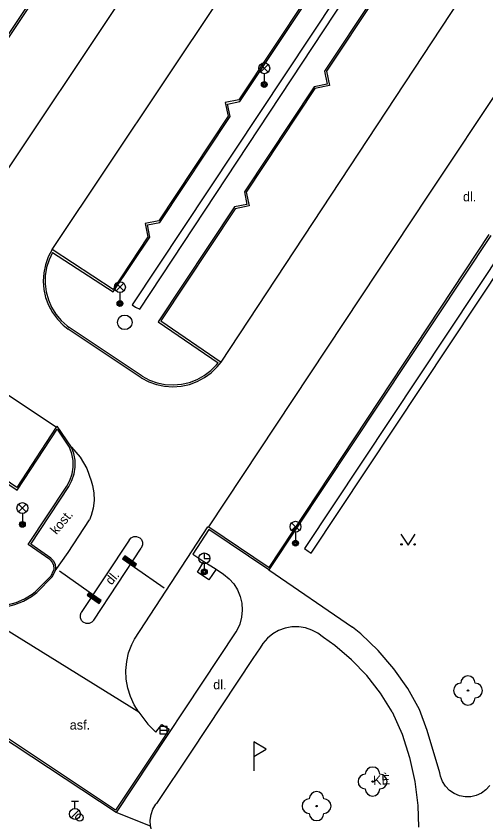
# Model space of a CAD drawing. Extents: x -539515 to -538098, y -1182060 to -1180157.
# Drawn here: x -538339.6 to -538307.3, y -1181540.3 to -1181484.8 of the extents above; entities that cross this region are included whole.
import ezdxf

# ---------------------------------------------------------------- set-up
doc = ezdxf.new("R2010")
doc.units = 0
for name, color, linetype in [('Vrstva 13', 7, 'Continuous'), ('Vrstva 22', 7, 'Continuous'), ('Vrstva 27', 7, 'Continuous'), ('Vrstva 28', 7, 'Continuous'), ('Vrstva 31', 7, 'Continuous'), ('Vrstva 33', 7, 'Continuous'), ('Vrstva 36', 7, 'Continuous'), ('Vrstva 40', 7, 'Continuous'), ('Vrstva 88', 7, 'Continuous')]:
    doc.layers.add(name, color=color, linetype=linetype)

msp = doc.modelspace()

# ---------------------------------------------------------------- linework, layer by layer
at = {"layer": 'Vrstva 13'}
for p, q in [((-538329.87, -1181470.61), (-538351.69, -1181503.32)), ((-538347.372, -1181506.094), (-538325.65, -1181473.54)), ((-538337.14, -1181500.86), (-538320.82, -1181476.41)), ((-538315.63, -1181480.58), (-538331.61, -1181504.66)), ((-538331.09, -1181504.96), (-538315.23, -1181480.93)), ((-538313.49, -1181481.218), (-538318.372, -1181488.571)), ((-538325.5, -1181508.61), (-538309.04, -1181483.64)), ((-538324.197, -1181490.668), (-538319.334, -1181483.335)), ((-538311.2, -1181497.12), (-538304.32, -1181486.74)), ((-538319.089, -1181489.652), (-538323.894, -1181496.889)), ((-538329.714, -1181498.989), (-538324.878, -1181491.694)), ((-538326.34, -1181519.96), (-538311.2, -1181497.12)), ((-538324.581, -1181497.924), (-538329.83, -1181505.83)), ((-538306.92, -1181499.89), (-538322.2, -1181522.92)), ((-538305.86, -1181500.51), (-538319.76, -1181521.45)), ((-538319.29, -1181521.77), (-538305.43, -1181500.87)), ((-538337.106, -1181501.059), (-538332.94, -1181503.77)), ((-538329.83, -1181505.83), (-538325.699, -1181508.657)), ((-538336.85, -1181513.09), (-538347.26, -1181506.17)), ((-538330.925, -1181509.577), (-538335.951, -1181506.227)), ((-538350.19, -1181510.38), (-538339.54, -1181517.42)), ((-538339.54, -1181517.42), (-538336.79, -1181513.23)), ((-538336.79, -1181513.23), (-538335.915, -1181514.522)), ((-538322.2, -1181522.92), (-538316.44, -1181526.85)), ((-538331.16, -1181532.72), (-538343.95, -1181524.79)), ((-538324.47, -1181527.17), (-538332.734, -1181539.625)), ((-538322.803, -1181528.276), (-538323.31, -1181529.01)), ((-538323.31, -1181529.01), (-538327.59, -1181535.47)), ((-538332.734, -1181539.625), (-538347.28, -1181530)), ((-538327.59, -1181535.47), (-538329.95, -1181539.01)), ((-538330.35, -1181540.57), (-538332.734, -1181539.625))]:
    msp.add_line(p, q, dxfattribs=at)
for points in [[(-538318.372, -1181488.571), (-538318.19, -1181489.47), (-538319.089, -1181489.652)], [(-538324.878, -1181491.694), (-538325.05, -1181490.84), (-538324.197, -1181490.668)], [(-538323.894, -1181496.889), (-538323.72, -1181497.75), (-538324.581, -1181497.924)], [(-538332.94, -1181503.77), (-538330.395, -1181500.016), (-538330.567, -1181499.162), (-538329.714, -1181498.989)], [(-538337.106, -1181501.059), (-538337.347, -1181501.566), (-538337.513, -1181502.103), (-538337.602, -1181502.658), (-538337.611, -1181503.22), (-538337.54, -1181503.778), (-538337.391, -1181504.32), (-538337.166, -1181504.835), (-538336.871, -1181505.314), (-538336.51, -1181505.745), (-538336.093, -1181506.121), (-538335.951, -1181506.227)], [(-538331.61, -1181504.66), (-538331.39, -1181504.82), (-538331.09, -1181504.96)], [(-538330.925, -1181509.577), (-538330.426, -1181509.84), (-538329.896, -1181510.03), (-538329.344, -1181510.143), (-538328.781, -1181510.177), (-538328.219, -1181510.131), (-538327.67, -1181510.006), (-538327.143, -1181509.804), (-538326.651, -1181509.53), (-538326.202, -1181509.189), (-538325.806, -1181508.788), (-538325.699, -1181508.657)], [(-538336.13, -1181517.157), (-538335.905, -1181516.75), (-538335.753, -1181516.311), (-538335.678, -1181515.852), (-538335.682, -1181515.387), (-538335.767, -1181514.93), (-538335.915, -1181514.522)], [(-538335.8, -1181514.46), (-538335.21, -1181515.153), (-538334.75, -1181515.939), (-538334.434, -1181516.793), (-538334.36, -1181517.1)], [(-538337.29, -1181522.2), (-538338.79, -1181521.16), (-538336.13, -1181517.157)], [(-538334.36, -1181517.1), (-538334.26, -1181517.613), (-538334.239, -1181518.135), (-538334.298, -1181518.655), (-538334.436, -1181519.159), (-538334.56, -1181519.46)], [(-538336.93, -1181522.99), (-538336.04, -1181521.71), (-538334.56, -1181519.46)], [(-538322.2, -1181522.92), (-538326.34, -1181520.14), (-538327.44, -1181521.83), (-538326.69, -1181522.33), (-538325.84, -1181522.87), (-538325.32, -1181523.22)], [(-538319.76, -1181521.45), (-538319.49, -1181521.62), (-538319.29, -1181521.77)], [(-538337.29, -1181522.2), (-538337.136, -1181522.376), (-538337.043, -1181522.6), (-538337.026, -1181522.842), (-538337.048, -1181522.959)], [(-538325.84, -1181522.87), (-538326.33, -1181523.59), (-538327.13, -1181523.07), (-538326.69, -1181522.33)], [(-538338.27, -1181524.401), (-538337.21, -1181523.321), (-538337.048, -1181522.959)], [(-538325.32, -1181523.22), (-538324.944, -1181523.524), (-538324.623, -1181523.885), (-538324.366, -1181524.295), (-538324.18, -1181524.741), (-538324.07, -1181525.21), (-538324.039, -1181525.694), (-538324.087, -1181526.175), (-538324.215, -1181526.641), (-538324.417, -1181527.08), (-538324.47, -1181527.17)], [(-538343.77, -1181524.73), (-538343.224, -1181525.021), (-538342.646, -1181525.239), (-538342.044, -1181525.38), (-538341.429, -1181525.443), (-538340.811, -1181525.426), (-538340.201, -1181525.329), (-538339.608, -1181525.154), (-538339.043, -1181524.904), (-538338.514, -1181524.584), (-538338.27, -1181524.401)], [(-538318.45, -1181527.57), (-538318.822, -1181527.279), (-538319.237, -1181527.054), (-538319.685, -1181526.903), (-538320.151, -1181526.829), (-538320.623, -1181526.835), (-538321.088, -1181526.921), (-538321.531, -1181527.083), (-538321.941, -1181527.318), (-538322.305, -1181527.619), (-538322.614, -1181527.977), (-538322.803, -1181528.276)], [(-538311.82, -1181532.52), (-538312.64, -1181531.079), (-538313.595, -1181529.724), (-538314.676, -1181528.468), (-538315.874, -1181527.321), (-538316.44, -1181526.85)], [(-538313.7, -1181532.69), (-538314.507, -1181531.397), (-538315.445, -1181530.195), (-538316.504, -1181529.098), (-538317.671, -1181528.118), (-538318.45, -1181527.57)], [(-538310.42, -1181536.88), (-538311.293, -1181533.963), (-538311.82, -1181532.52)], [(-538313.7, -1181532.69), (-538313.031, -1181534.234), (-538312.512, -1181535.834), (-538312.148, -1181537.476), (-538311.94, -1181539.146), (-538311.89, -1181540.63)], [(-538306.99, -1181537.76), (-538307.251, -1181538.05), (-538307.565, -1181538.281), (-538307.919, -1181538.443), (-538308.299, -1181538.53), (-538308.689, -1181538.537), (-538309.072, -1181538.465), (-538309.433, -1181538.316), (-538309.755, -1181538.097), (-538310.027, -1181537.817), (-538310.235, -1181537.488), (-538310.373, -1181537.123), (-538310.42, -1181536.88)], [(-538329.19, -1181542), (-538329.535, -1181541.815), (-538329.836, -1181541.564), (-538330.079, -1181541.258), (-538330.255, -1181540.908), (-538330.35, -1181540.57), (-538330.38, -1181540.139), (-538330.323, -1181539.752), (-538330.189, -1181539.384), (-538329.983, -1181539.051), (-538329.95, -1181539.01)]]:
    msp.add_lwpolyline(points, dxfattribs=at)
at = {"layer": 'Vrstva 22'}
for centre in [(-538308.49, -1181531.22), (-538315.06, -1181537.49), (-538318.92, -1181539.18)]:
    msp.add_circle(centre, 0.05, dxfattribs=at)
for centre, start, end in [((-538308.49, -1181530.72), 0, 180), ((-538308.99, -1181531.22), 90, 270), ((-538307.99, -1181531.22), 270, 90), ((-538308.49, -1181531.72), 180, 0), ((-538315.56, -1181537.49), 90, 270), ((-538315.06, -1181536.99), 0, 180), ((-538314.56, -1181537.49), 270, 90), ((-538315.06, -1181537.99), 180, 0), ((-538319.42, -1181539.18), 90, 270), ((-538318.92, -1181538.68), 0, 180), ((-538318.42, -1181539.18), 270, 90), ((-538318.92, -1181539.68), 180, 0)]:
    msp.add_arc(centre, 0.5, start, end, dxfattribs=at)
at = {"layer": 'Vrstva 27'}
msp.add_line((-538329.72, -1181533.95), (-538329.22, -1181533.95), dxfattribs=at)
msp.add_lwpolyline([(-538329.72, -1181534.2), (-538329.22, -1181534.2), (-538329.22, -1181533.7), (-538329.72, -1181533.7)], close=True, dxfattribs=at)
msp.add_circle((-538332.13, -1181505.87), 0.5, dxfattribs=at)
at = {"layer": 'Vrstva 28'}
for p, q in [((-538335.81, -1181538.845), (-538335.31, -1181538.845)), ((-538335.56, -1181539.345), (-538335.56, -1181538.845)), ((-538335.818, -1181539.992), (-538335.288, -1181539.462))]:
    msp.add_line(p, q, dxfattribs=at)
for centre, radius in [((-538335.56, -1181539.72), 0.375), ((-538335.24, -1181539.97), 0.25)]:
    msp.add_circle(centre, radius, dxfattribs=at)
at = {"layer": 'Vrstva 31'}
msp.add_line((-538323.25, -1181535.76), (-538323.25, -1181536.76), dxfattribs=at)
msp.add_lwpolyline([(-538323.25, -1181534.76), (-538323.25, -1181535.76), (-538322.384, -1181535.26)], close=True, dxfattribs=at)
at = {"layer": 'Vrstva 33'}
for p, q in [((-538322.785, -1181488.64), (-538322.255, -1181488.11)), ((-538322.785, -1181488.11), (-538322.255, -1181488.64)), ((-538322.52, -1181488.75), (-538322.52, -1181489.5)), ((-538332.725, -1181503.71), (-538332.195, -1181503.18)), ((-538332.725, -1181503.18), (-538332.195, -1181503.71)), ((-538332.46, -1181503.82), (-538332.46, -1181504.57)), ((-538339.445, -1181518.92), (-538338.915, -1181518.39)), ((-538339.445, -1181518.39), (-538338.915, -1181518.92)), ((-538339.18, -1181519.03), (-538339.18, -1181519.78)), ((-538320.635, -1181520.21), (-538320.105, -1181519.68)), ((-538320.635, -1181519.68), (-538320.105, -1181520.21)), ((-538320.37, -1181520.32), (-538320.37, -1181521.07)), ((-538326.65, -1181522.5), (-538326.65, -1181522.85)), ((-538334.579, -1181524.446), (-538336.627, -1181523.012)), ((-538331.461, -1181522.724), (-538329.413, -1181524.158))]:
    msp.add_line(p, q, dxfattribs=at)
for points in [[(-538332.28, -1181522.15), (-538331.461, -1181522.724), (-538331.317, -1181522.519), (-538332.137, -1181521.945)], [(-538332.21, -1181522.138), (-538331.473, -1181522.654), (-538331.387, -1181522.531), (-538332.124, -1181522.015)], [(-538332.141, -1181522.125), (-538331.485, -1181522.584), (-538331.457, -1181522.543), (-538332.112, -1181522.084)], [(-538333.76, -1181525.02), (-538334.579, -1181524.446), (-538334.723, -1181524.651), (-538333.903, -1181525.225)], [(-538333.83, -1181525.032), (-538334.567, -1181524.516), (-538334.653, -1181524.639), (-538333.916, -1181525.155)], [(-538333.899, -1181525.045), (-538334.555, -1181524.586), (-538334.583, -1181524.627), (-538333.928, -1181525.086)]]:
    msp.add_lwpolyline(points, close=True, dxfattribs=at)
msp.add_lwpolyline([(-538326.65, -1181521.75), (-538326.65, -1181522.125), (-538326.275, -1181522.125)], dxfattribs=at)
for centre, radius in [((-538322.52, -1181488.375), 0.375), ((-538322.52, -1181489.5), 0.2), ((-538322.52, -1181489.5), 0.145), ((-538322.52, -1181489.5), 0.0876), ((-538332.46, -1181503.445), 0.375), ((-538332.46, -1181504.57), 0.2), ((-538332.46, -1181504.57), 0.145), ((-538332.46, -1181504.57), 0.0876), ((-538339.18, -1181518.655), 0.375), ((-538339.18, -1181519.78), 0.2), ((-538339.18, -1181519.78), 0.145), ((-538339.18, -1181519.78), 0.0876), ((-538320.37, -1181519.945), 0.375), ((-538320.37, -1181521.07), 0.2), ((-538320.37, -1181521.07), 0.145), ((-538320.37, -1181521.07), 0.0876), ((-538326.65, -1181522.125), 0.375), ((-538326.65, -1181523.05), 0.2), ((-538326.65, -1181523.05), 0.145), ((-538326.65, -1181523.05), 0.0876)]:
    msp.add_circle(centre, radius, dxfattribs=at)
at = {"layer": 'Vrstva 36'}
msp.add_lwpolyline([(-538313.118, -1181520.465), (-538312.618, -1181521.215), (-538312.118, -1181520.465)], dxfattribs=at)
for centre in [(-538313.068, -1181521.165), (-538312.169, -1181521.165)]:
    msp.add_circle(centre, 0.05, dxfattribs=at)
at = {"layer": 'Vrstva 88'}
for p, q in [((-538351.5, -1181503.28), (-538329.73, -1181470.68)), ((-538313.435, -1181481.339), (-538318.238, -1181488.576)), ((-538319.469, -1181483.321), (-538324.267, -1181490.549)), ((-538319.033, -1181489.773), (-538323.76, -1181496.896)), ((-538325.014, -1181491.675), (-538329.789, -1181498.872)), ((-538324.523, -1181498.045), (-538329.65, -1181505.77)), ((-538322.18, -1181522.76), (-538307.02, -1181499.82)), ((-538332.93, -1181503.6), (-538337.14, -1181500.86)), ((-538330.99, -1181509.69), (-538336.03, -1181506.33)), ((-538339.56, -1181517.25), (-538349.97, -1181510.35)), ((-538335.8, -1181514.46), (-538336.78, -1181513.03)), ((-538335.1, -1181537.89), (-538367.65, -1181516.28)), ((-538331.47, -1181527.68), (-538326.4, -1181519.96)), ((-538326.4, -1181519.96), (-538326.34, -1181519.96)), ((-538326.34, -1181519.96), (-538322.18, -1181522.76)), ((-538331.82, -1181520.86), (-538335.13, -1181525.85)), ((-538334.26, -1181526.37), (-538331, -1181521.42)), ((-538329.41, -1181534.43), (-538332.77, -1181539.45)), ((-538332.77, -1181539.45), (-538335.1, -1181537.89))]:
    msp.add_line(p, q, dxfattribs=at)
for points in [[(-538318.238, -1181488.576), (-538318.037, -1181489.572), (-538319.033, -1181489.773)], [(-538324.267, -1181490.549), (-538325.203, -1181490.738), (-538325.014, -1181491.675)], [(-538323.76, -1181496.896), (-538323.567, -1181497.852), (-538324.523, -1181498.045)], [(-538329.789, -1181498.872), (-538330.72, -1181499.06), (-538330.532, -1181499.991), (-538332.93, -1181503.6)], [(-538337.14, -1181500.86), (-538337.405, -1181501.366), (-538337.596, -1181501.904), (-538337.711, -1181502.464), (-538337.747, -1181503.034), (-538337.702, -1181503.604), (-538337.579, -1181504.161), (-538337.379, -1181504.697), (-538337.106, -1181505.198), (-538336.766, -1181505.657), (-538336.365, -1181506.064), (-538336.03, -1181506.33)], [(-538329.65, -1181505.77), (-538325.5, -1181508.61)], [(-538330.99, -1181509.69), (-538330.483, -1181509.957), (-538329.945, -1181510.152), (-538329.384, -1181510.269), (-538328.813, -1181510.307), (-538328.241, -1181510.265), (-538327.681, -1181510.145), (-538327.144, -1181509.947), (-538326.639, -1181509.677), (-538326.176, -1181509.339), (-538325.766, -1181508.94), (-538325.5, -1181508.61)], [(-538336.78, -1181513.03), (-538336.85, -1181513.09), (-538339.56, -1181517.25)], [(-538335.99, -1181517.18), (-538335.767, -1181516.759), (-538335.618, -1181516.307), (-538335.546, -1181515.837), (-538335.554, -1181515.361), (-538335.642, -1181514.893), (-538335.8, -1181514.46)], [(-538337.22, -1181522.1), (-538338.59, -1181521.15), (-538335.99, -1181517.18)], [(-538331.82, -1181520.86), (-538331.689, -1181520.711), (-538331.51, -1181520.624), (-538331.312, -1181520.614), (-538331.1, -1181520.7), (-538330.981, -1181520.819), (-538330.901, -1181521.001), (-538330.898, -1181521.199), (-538331, -1181521.42)], [(-538337.22, -1181522.1), (-538337.044, -1181522.294), (-538336.935, -1181522.532), (-538336.901, -1181522.791), (-538336.93, -1181522.99)], [(-538338.19, -1181524.48), (-538337.1, -1181523.37), (-538336.93, -1181522.99)], [(-538343.95, -1181524.79), (-538343.395, -1181525.092), (-538342.806, -1181525.322), (-538342.193, -1181525.475), (-538341.566, -1181525.55), (-538340.934, -1181525.545), (-538340.308, -1181525.46), (-538339.698, -1181525.297), (-538339.113, -1181525.059), (-538338.562, -1181524.748), (-538338.19, -1181524.48)], [(-538334.26, -1181526.37), (-538334.396, -1181526.517), (-538334.578, -1181526.6), (-538334.778, -1181526.606), (-538335, -1181526.51), (-538335.11, -1181526.395), (-538335.189, -1181526.211), (-538335.191, -1181526.011), (-538335.13, -1181525.85)], [(-538331.16, -1181532.72), (-538331.486, -1181532.199), (-538331.743, -1181531.641), (-538331.924, -1181531.054), (-538332.028, -1181530.448), (-538332.052, -1181529.834), (-538331.996, -1181529.222), (-538331.862, -1181528.622), (-538331.651, -1181528.045), (-538331.47, -1181527.68)], [(-538331.16, -1181532.72), (-538330.546, -1181533.538), (-538330, -1181534.09)], [(-538330, -1181534.09), (-538329.58, -1181533.56), (-538329.07, -1181533.87), (-538329.41, -1181534.43)]]:
    msp.add_lwpolyline(points, dxfattribs=at)

# ---------------------------------------------------------------- texts
at = {"layer": 'Vrstva 40'}
for s, p in [('dl.', (-538308.833, -1181497.539)), ('dl.', (-538326.037, -1181531.138)), ('asf.', (-538335.92, -1181533.912))]:
    msp.add_text(s, height=0.65, dxfattribs=at).set_placement(p)
for s, rotation, p in [('kost.', 50, (-538336.83, -1181520.528)), ('dl.', 50, (-538333.048, -1181524.002)), ('KEØ', 2.8766, (-538315.012, -1181537.732))]:
    msp.add_text(s, height=0.65, rotation=rotation, dxfattribs=at).set_placement(p)

doc.saveas('drawing.dxf')
